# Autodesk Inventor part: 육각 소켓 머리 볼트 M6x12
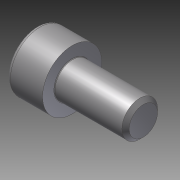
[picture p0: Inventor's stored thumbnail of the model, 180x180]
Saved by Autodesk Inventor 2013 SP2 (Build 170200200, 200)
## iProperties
Created: 2024-07
Part Number: 육각 소켓 머리 볼트 M6x12
Material: Generic
Document SubType Name: Modeling
Designer: 601
Density: 1 g/cm^3
Author: 601
변환 표준: STEP AP214IS
전처리기: Build: 200, Release: 2013 SP2 Update 6 - Date: Thu 07/17/2014
전송 단위: 밀리미터
불확실성: 0.01
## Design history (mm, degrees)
node "육각 소켓 머리 볼트 M6x121"
body "Solid1"
node "기준1"
